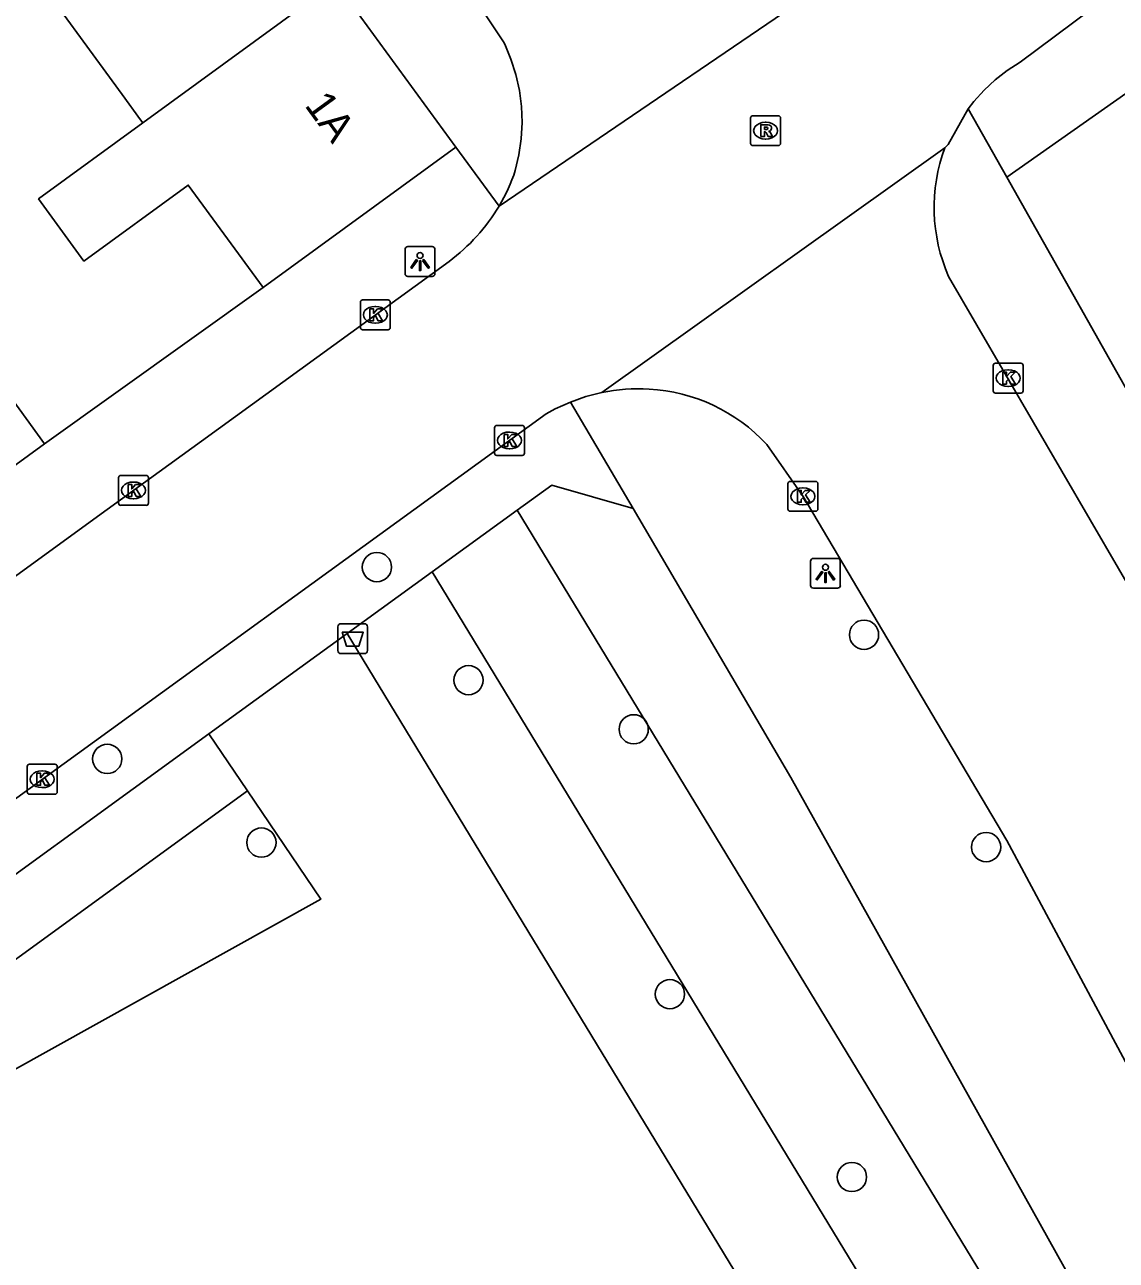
# Model space of a CAD drawing. Extents: x 159222 to 160346, y 381249 to 382166.
# Drawn here: x 159768.58 to 159805.07, y 381427.03 to 381468.35 of the extents above; entities that cross this region are included whole.
import ezdxf

# ---------------------------------------------------------------- set-up
doc = ezdxf.new("R2010")
doc.units = 0
for name, color, linetype in [('IMGEO_Afvalbak', 7, 'Continuous'), ('IMGEO_Boom', 7, 'Continuous'), ('IMGEO_Groenvoorziening', 7, 'Continuous'), ('IMGEO_Kolk', 7, 'Continuous'), ('IMGEO_Lichtpunt', 7, 'Continuous'), ('IMGEO_Muur', 7, 'Continuous'), ('IMGEO_Pand', 7, 'Continuous'), ('IMGEO_Pand_nummerreeks', 7, 'Continuous'), ('IMGEO_Rijbaan_lokaal_gesloten', 7, 'Continuous'), ('IMGEO_Rijbaan_lokaal_open', 7, 'Continuous'), ('IMGEO_Rioolput', 7, 'Continuous'), ('IMGEO_Voetpad_open', 7, 'Continuous')]:
    doc.layers.add(name, color=color, linetype=linetype)

msp = doc.modelspace()

# ---------------------------------------------------------------- linework, layer by layer
at = {"layer": 'IMGEO_Afvalbak'}
for p, q in [((159779.046, 381447.418), (159779.046, 381448.218)), ((159779.046, 381448.218), (159779.046, 381447.418)), ((159779.146, 381448.318), (159779.936, 381448.318)), ((159779.936, 381448.318), (159779.146, 381448.318)), ((159780.036, 381448.218), (159780.036, 381447.418)), ((159780.036, 381447.418), (159780.036, 381448.218)), ((159779.936, 381447.318), (159779.146, 381447.318)), ((159779.146, 381447.318), (159779.936, 381447.318))]:
    msp.add_line(p, q, dxfattribs=at)
msp.add_lwpolyline([(159779.189, 381448.032), (159779.893, 381448.032), (159779.744, 381447.562), (159779.338, 381447.562), (159779.189, 381448.032)], dxfattribs=at)
for centre, start, end in [((159779.146, 381448.218), 90, 180), ((159779.146, 381448.218), 90, 180), ((159779.936, 381448.218), 0, 90), ((159779.936, 381448.218), 360, 90), ((159779.146, 381447.418), 180, 270), ((159779.146, 381447.418), 180, 270), ((159779.936, 381447.418), 270, 0), ((159779.936, 381447.418), 270, 0)]:
    msp.add_arc(centre, 0.1, start, end, dxfattribs=at)
at = {"layer": 'IMGEO_Boom'}
for centre in [(159780.351, 381450.212), (159796.633, 381447.95), (159783.412, 381446.43), (159788.934, 381444.787), (159771.337, 381443.797), (159776.488, 381440.997), (159800.715, 381440.846), (159790.146, 381435.928), (159796.229, 381429.812)]:
    msp.add_circle(centre, 0.489, dxfattribs=at)
at = {"layer": 'IMGEO_Groenvoorziening'}
for points in [[(159785.037, 381452.114), (159802.511, 381423.35)], [(159799.442, 381421.661), (159782.195, 381450.052)], [(159779.353, 381447.989), (159783.63, 381440.949), (159796.372, 381419.973)], [(159774.733, 381444.636), (159776.021, 381442.729)], [(159745.234, 381420.346), (159776.021, 381442.729)], [(159776.021, 381442.729), (159778.473, 381439.101), (159748.724, 381422.549), (159746.885, 381417.737)]]:
    msp.add_lwpolyline(points, dxfattribs=at)
at = {"layer": 'IMGEO_Kolk'}
for p, q in [((159779.797, 381458.223), (159779.797, 381459.075)), ((159779.872, 381459.149), (159780.724, 381459.149)), ((159780.285, 381458.929), (159780.31, 381458.929)), ((159780.798, 381459.075), (159780.798, 381458.223)), ((159780.724, 381458.149), (159779.872, 381458.149)), ((159780.308, 381458.369), (159780.283, 381458.369)), ((159800.951, 381456.107), (159800.951, 381456.959)), ((159801.026, 381457.033), (159801.878, 381457.033)), ((159801.952, 381456.959), (159801.952, 381456.107)), ((159801.439, 381456.813), (159801.464, 381456.813)), ((159801.462, 381456.253), (159801.437, 381456.253)), ((159801.878, 381456.033), (159801.026, 381456.033)), ((159784.281, 381454.023), (159784.281, 381454.875)), ((159784.356, 381454.949), (159785.208, 381454.949)), ((159785.282, 381454.875), (159785.282, 381454.023)), ((159784.769, 381454.729), (159784.794, 381454.729)), ((159784.792, 381454.169), (159784.767, 381454.169)), ((159785.208, 381453.949), (159784.356, 381453.949)), ((159771.711, 381452.352), (159771.711, 381453.204)), ((159771.786, 381453.278), (159772.638, 381453.278)), ((159772.712, 381453.204), (159772.712, 381452.352)), ((159772.199, 381453.058), (159772.224, 381453.058)), ((159794.09, 381452.153), (159794.09, 381453.005)), ((159794.165, 381453.079), (159795.017, 381453.079)), ((159794.578, 381452.859), (159794.603, 381452.859)), ((159795.091, 381453.005), (159795.091, 381452.153)), ((159772.222, 381452.498), (159772.197, 381452.498)), ((159772.638, 381452.278), (159771.786, 381452.278)), ((159795.017, 381452.079), (159794.165, 381452.079)), ((159794.601, 381452.299), (159794.576, 381452.299)), ((159768.661, 381442.69), (159768.661, 381443.542)), ((159768.736, 381443.616), (159769.588, 381443.616)), ((159769.149, 381443.396), (159769.174, 381443.396)), ((159769.662, 381443.542), (159769.662, 381442.69)), ((159769.172, 381442.836), (159769.147, 381442.836)), ((159769.588, 381442.616), (159768.736, 381442.616))]:
    msp.add_line(p, q, dxfattribs=at)
for points in [[(159779.797, 381458.223), (159779.797, 381459.075)], [(159779.872, 381459.149), (159780.724, 381459.149)], [(159780.798, 381459.075), (159780.798, 381458.223)], [(159780.118, 381458.849), (159780.241, 381458.849), (159780.241, 381458.698), (159780.371, 381458.849), (159780.535, 381458.849), (159780.389, 381458.698), (159780.542, 381458.449), (159780.39, 381458.449), (159780.305, 381458.613), (159780.241, 381458.546), (159780.241, 381458.449), (159780.118, 381458.449), (159780.118, 381458.849)], [(159780.724, 381458.149), (159779.872, 381458.149)], [(159800.951, 381456.107), (159800.951, 381456.959)], [(159801.026, 381457.033), (159801.878, 381457.033)], [(159801.952, 381456.959), (159801.952, 381456.107)], [(159801.272, 381456.733), (159801.395, 381456.733), (159801.395, 381456.582), (159801.525, 381456.733), (159801.689, 381456.733), (159801.543, 381456.582), (159801.696, 381456.333), (159801.544, 381456.333), (159801.459, 381456.497), (159801.395, 381456.43), (159801.395, 381456.333), (159801.272, 381456.333), (159801.272, 381456.733)], [(159801.878, 381456.033), (159801.026, 381456.033)], [(159784.281, 381454.023), (159784.281, 381454.875)], [(159784.356, 381454.949), (159785.208, 381454.949)], [(159785.282, 381454.875), (159785.282, 381454.023)], [(159784.602, 381454.649), (159784.725, 381454.649), (159784.725, 381454.498), (159784.855, 381454.649), (159785.019, 381454.649), (159784.873, 381454.498), (159785.026, 381454.249), (159784.874, 381454.249), (159784.789, 381454.413), (159784.725, 381454.346), (159784.725, 381454.249), (159784.602, 381454.249), (159784.602, 381454.649)], [(159785.208, 381453.949), (159784.356, 381453.949)], [(159771.711, 381452.352), (159771.711, 381453.204)], [(159771.786, 381453.278), (159772.638, 381453.278)], [(159772.712, 381453.204), (159772.712, 381452.352)], [(159772.032, 381452.978), (159772.155, 381452.978), (159772.155, 381452.827), (159772.285, 381452.978), (159772.449, 381452.978), (159772.303, 381452.827), (159772.456, 381452.578), (159772.304, 381452.578), (159772.219, 381452.742), (159772.155, 381452.675), (159772.155, 381452.578), (159772.032, 381452.578), (159772.032, 381452.978)], [(159794.09, 381452.153), (159794.09, 381453.005)], [(159794.165, 381453.079), (159795.017, 381453.079)], [(159794.411, 381452.779), (159794.534, 381452.779), (159794.534, 381452.628), (159794.664, 381452.779), (159794.828, 381452.779), (159794.682, 381452.628), (159794.835, 381452.379), (159794.683, 381452.379), (159794.598, 381452.543), (159794.534, 381452.476), (159794.534, 381452.379), (159794.411, 381452.379), (159794.411, 381452.779)], [(159795.091, 381453.005), (159795.091, 381452.153)], [(159772.638, 381452.278), (159771.786, 381452.278)], [(159795.017, 381452.079), (159794.165, 381452.079)], [(159768.661, 381442.69), (159768.661, 381443.542)], [(159768.736, 381443.616), (159769.588, 381443.616)], [(159768.982, 381443.316), (159769.105, 381443.316), (159769.105, 381443.165), (159769.235, 381443.316), (159769.399, 381443.316), (159769.253, 381443.165), (159769.406, 381442.916), (159769.254, 381442.916), (159769.169, 381443.08), (159769.105, 381443.013), (159769.105, 381442.916), (159768.982, 381442.916), (159768.982, 381443.316)], [(159769.662, 381443.542), (159769.662, 381442.69)], [(159769.588, 381442.616), (159768.736, 381442.616)]]:
    msp.add_lwpolyline(points, dxfattribs=at)
for centre, start, end in [((159779.874, 381459.073), 91.552, 178.448), ((159779.874, 381459.073), 91.552, 178.448), ((159780.722, 381459.073), 1.552, 88.448), ((159780.722, 381459.073), 1.552, 88.448), ((159779.874, 381458.225), 181.552, 268.448), ((159779.874, 381458.225), 181.552, 268.448), ((159780.722, 381458.225), 271.552, 358.448), ((159780.722, 381458.225), 271.552, 358.448), ((159801.028, 381456.957), 91.552, 178.448), ((159801.028, 381456.957), 91.552, 178.448), ((159801.876, 381456.957), 1.552, 88.448), ((159801.876, 381456.957), 1.552, 88.448), ((159801.028, 381456.109), 181.552, 268.448), ((159801.028, 381456.109), 181.552, 268.448), ((159801.876, 381456.109), 271.552, 358.448), ((159801.876, 381456.109), 271.552, 358.448), ((159784.358, 381454.873), 91.552, 178.448), ((159784.358, 381454.873), 91.552, 178.448), ((159785.206, 381454.873), 1.552, 88.448), ((159785.206, 381454.873), 1.552, 88.448), ((159784.358, 381454.025), 181.552, 268.448), ((159784.358, 381454.025), 181.552, 268.448), ((159785.206, 381454.025), 271.552, 358.448), ((159785.206, 381454.025), 271.552, 358.448), ((159771.788, 381453.202), 91.552, 178.448), ((159771.788, 381453.202), 91.552, 178.448), ((159772.636, 381453.202), 1.552, 88.448), ((159772.636, 381453.202), 1.552, 88.448), ((159794.167, 381453.003), 91.552, 178.448), ((159794.167, 381453.003), 91.552, 178.448), ((159795.015, 381453.003), 1.552, 88.448), ((159795.015, 381453.003), 1.552, 88.448), ((159771.788, 381452.354), 181.552, 268.448), ((159771.788, 381452.354), 181.552, 268.448), ((159772.636, 381452.354), 271.552, 358.448), ((159772.636, 381452.354), 271.552, 358.448), ((159794.167, 381452.155), 181.552, 268.448), ((159794.167, 381452.155), 181.552, 268.448), ((159795.015, 381452.155), 271.552, 358.448), ((159795.015, 381452.155), 271.552, 358.448), ((159768.738, 381443.54), 91.552, 178.448), ((159768.738, 381443.54), 91.552, 178.448), ((159769.586, 381443.54), 1.552, 88.448), ((159769.586, 381443.54), 1.552, 88.448), ((159768.738, 381442.692), 181.552, 268.448), ((159768.738, 381442.692), 181.552, 268.448), ((159769.586, 381442.692), 271.552, 358.448), ((159769.586, 381442.692), 271.552, 358.448)]:
    msp.add_arc(centre, 0.0765, start, end, dxfattribs=at)
for centre, major_axis, ratio, start_param, end_param in [((159780.284, 381458.649), (-0.387, 0.002), 0.722429, 4.712389, 7.853982), ((159780.309, 381458.649), (-0.39, 0.002), 0.717154, 1.570796, 4.712389), ((159801.438, 381456.533), (-0.387, 0.002), 0.722429, 4.712389, 7.853982), ((159801.463, 381456.533), (-0.39, 0.002), 0.717154, 1.570796, 4.712389), ((159784.768, 381454.449), (-0.387, 0.002), 0.722429, 4.712389, 7.853982), ((159784.793, 381454.449), (-0.39, 0.002), 0.717154, 1.570796, 4.712389), ((159772.198, 381452.778), (-0.387, 0.002), 0.722429, 4.712389, 7.853982), ((159772.223, 381452.778), (-0.39, 0.002), 0.717154, 1.570796, 4.712389), ((159794.577, 381452.579), (-0.387, 0.002), 0.722429, 4.712389, 7.853982), ((159794.602, 381452.579), (-0.39, 0.002), 0.717154, 1.570796, 4.712389), ((159769.148, 381443.116), (-0.387, 0.002), 0.722429, 4.712389, 7.853982), ((159769.173, 381443.116), (-0.39, 0.002), 0.717154, 1.570796, 4.712389)]:
    msp.add_ellipse(centre, major_axis=major_axis, ratio=ratio, start_param=start_param, end_param=end_param, dxfattribs=at)
at = {"layer": 'IMGEO_Lichtpunt'}
for p, q in [((159781.293, 381460.836), (159781.293, 381460.029)), ((159781.293, 381460.836), (159781.293, 381460.029)), ((159782.195, 381460.931), (159781.387, 381460.931)), ((159782.195, 381460.931), (159781.387, 381460.931)), ((159782.289, 381460.029), (159782.289, 381460.836)), ((159782.289, 381460.029), (159782.289, 381460.836)), ((159781.387, 381459.935), (159782.195, 381459.935)), ((159781.387, 381459.935), (159782.195, 381459.935)), ((159794.845, 381450.407), (159794.845, 381449.6)), ((159794.845, 381450.407), (159794.845, 381449.6)), ((159795.747, 381450.502), (159794.939, 381450.502)), ((159795.747, 381450.502), (159794.939, 381450.502)), ((159795.841, 381449.6), (159795.841, 381450.407)), ((159795.841, 381449.6), (159795.841, 381450.407)), ((159794.939, 381449.506), (159795.747, 381449.506)), ((159794.939, 381449.506), (159795.747, 381449.506))]:
    msp.add_line(p, q, dxfattribs=at)
for points in [[(159781.667, 381460.5), (159781.706, 381460.472), (159781.518, 381460.21), (159781.48, 381460.237), (159781.667, 381460.5)], [(159781.769, 381460.452), (159781.816, 381460.452), (159781.816, 381460.13), (159781.769, 381460.13), (159781.769, 381460.452)], [(159781.879, 381460.472), (159781.917, 381460.499), (159782.104, 381460.237), (159782.065, 381460.209), (159781.879, 381460.472)], [(159795.219, 381450.071), (159795.258, 381450.043), (159795.07, 381449.781), (159795.032, 381449.808), (159795.219, 381450.071)], [(159795.321, 381450.023), (159795.368, 381450.023), (159795.368, 381449.701), (159795.321, 381449.701), (159795.321, 381450.023)], [(159795.431, 381450.043), (159795.469, 381450.07), (159795.656, 381449.808), (159795.617, 381449.78), (159795.431, 381450.043)]]:
    msp.add_lwpolyline(points, dxfattribs=at)
for centre in [(159781.792, 381460.634), (159795.344, 381450.205)]:
    msp.add_circle(centre, 0.0994, dxfattribs=at)
for centre, start, end in [((159781.387, 381460.836), 90, 180), ((159781.387, 381460.836), 90, 180), ((159782.195, 381460.836), 0, 90), ((159782.195, 381460.836), 0, 90), ((159781.387, 381460.029), 180, 270), ((159781.387, 381460.029), 180, 270), ((159782.195, 381460.029), 270, 0), ((159782.195, 381460.029), 270, 360), ((159794.939, 381450.407), 90, 180), ((159794.939, 381450.407), 90, 180), ((159795.747, 381450.407), 0, 90), ((159795.747, 381450.407), 0, 90), ((159794.939, 381449.6), 180, 270), ((159794.939, 381449.6), 180, 270), ((159795.747, 381449.6), 270, 0), ((159795.747, 381449.6), 270, 360)]:
    msp.add_arc(centre, 0.0946, start, end, dxfattribs=at)
at = {"layer": 'IMGEO_Muur'}
msp.add_lwpolyline([(159769.241, 381454.339), (159776.549, 381459.559)], dxfattribs=at)
at = {"layer": 'IMGEO_Pand'}
for points in [[(159801.406, 381463.25), (159812.627, 381471.155), (159814.489, 381472.466)], [(159768.589, 381470.465), (159771.832, 381466.021), (159772.451, 381465.173), (159772.525, 381465.072)], [(159778.966, 381469.772), (159772.525, 381465.072)], [(159778.966, 381469.772), (159782.989, 381464.259)], [(159772.525, 381465.072), (159769.038, 381462.527), (159770.555, 381460.447), (159774.043, 381462.992), (159776.549, 381459.559)], [(159782.989, 381464.259), (159776.549, 381459.559)], [(159809.148, 381449.52), (159801.406, 381463.25)], [(159762.739, 381457.872), (159765.318, 381459.744), (159769.241, 381454.339)], [(159769.241, 381454.339), (159766.676, 381452.477)]]:
    msp.add_lwpolyline(points, dxfattribs=at)
at = {"layer": 'IMGEO_Rijbaan_lokaal_gesloten'}
for points in [[(159787.872, 381456.049), (159799.332, 381464.238)], [(159799.461, 381459.93), (159807.03, 381446.91)], [(159807.676, 381429.366), (159801.407, 381441.063), (159794.594, 381452.576), (159793.382, 381454.313)]]:
    msp.add_lwpolyline(points, dxfattribs=at)
for centre, radius, start, end in [((159804.758, 381462.245), 5.781, 159.8284, 203.6019), ((159789.123, 381449.926), 6.25, 87.0179, 101.546), ((159789.118, 381450.367), 5.81, 42.7866, 86.7466)]:
    msp.add_arc(centre, radius, start, end, dxfattribs=at)
at = {"layer": 'IMGEO_Rijbaan_lokaal_open'}
for points in [[(159800.114, 381465.542), (159800.306, 381465.789), (159800.646, 381466.167), (159801.019, 381466.514), (159801.421, 381466.825), (159801.849, 381467.1), (159808.9, 381472.368), (159810.846, 381473.748), (159812.928, 381475.224), (159813.774, 381475.824), (159816.088, 381477.412), (159825.099, 381483.598), (159827.05, 381484.957), (159830.152, 381487.119), (159834.029, 381489.821)], [(159774.841, 381481.496), (159775.507, 381480.628), (159780.458, 381473.977), (159784.579, 381467.786), (159784.622, 381467.698), (159784.831, 381467.199), (159784.994, 381466.684), (159785.111, 381466.156), (159785.18, 381465.62), (159785.201, 381465.08), (159785.174, 381464.54), (159785.099, 381464.004), (159784.976, 381463.478)], [(159784.432, 381462.289), (159797.283, 381471.041)], [(159800.114, 381465.542), (159799.442, 381464.347), (159799.332, 381464.238)], [(159762.389, 381445.632), (159765.811, 381448.121), (159771.014, 381451.905), (159774.481, 381454.427), (159782.761, 381460.436)], [(159786.816, 381455.733), (159787.337, 381455.915), (159787.872, 381456.049)], [(159765.923, 381440.763), (159767.044, 381441.581), (159786.01, 381455.342), (159786.313, 381455.506), (159786.816, 381455.733)]]:
    msp.add_lwpolyline(points, dxfattribs=at)
for centre, radius, start, end in [((159779.041, 381465.474), 6.262, 329.4216, 341.4076), ((159779.029, 381465.481), 6.275, 306.489, 329.4239)]:
    msp.add_arc(centre, radius, start, end, dxfattribs=at)
at = {"layer": 'IMGEO_Rioolput'}
for p, q in [((159792.843, 381464.384), (159792.843, 381465.236)), ((159792.918, 381465.31), (159793.77, 381465.31)), ((159793.844, 381465.236), (159793.844, 381464.384)), ((159793.331, 381465.09), (159793.356, 381465.09)), ((159793.77, 381464.31), (159792.918, 381464.31)), ((159793.354, 381464.53), (159793.329, 381464.53))]:
    msp.add_line(p, q, dxfattribs=at)
for points in [[(159792.843, 381464.384), (159792.843, 381465.236)], [(159792.918, 381465.31), (159793.77, 381465.31)], [(159793.844, 381465.236), (159793.844, 381464.384)], [(159793.432, 381465.008), (159793.18, 381465.01), (159793.18, 381464.61)], [(159793.18, 381464.61), (159793.304, 381464.61), (159793.304, 381464.772), (159793.315, 381464.772)], [(159793.358, 381464.929), (159793.304, 381464.929), (159793.304, 381464.848)], [(159793.304, 381464.848), (159793.356, 381464.848)], [(159793.362, 381464.743), (159793.433, 381464.61), (159793.573, 381464.61), (159793.508, 381464.736)], [(159793.77, 381464.31), (159792.918, 381464.31)]]:
    msp.add_lwpolyline(points, dxfattribs=at)
for centre, radius, start, end in [((159792.92, 381465.234), 0.0765, 91.552, 178.448), ((159792.92, 381465.234), 0.0765, 91.552, 178.448), ((159793.768, 381465.234), 0.0765, 1.552, 88.448), ((159793.768, 381465.234), 0.0765, 1.552, 88.448), ((159793.314, 381464.719), 0.0533, 26.0293, 88.6989), ((159793.34, 381465.037), 0.19, 274.7715, 282.9687), ((159793.364, 381464.833), 0.0964, 77.0061, 93.1865), ((159793.378, 381464.89), 0.0378, 276.6634, 79.6772), ((159793.431, 381464.898), 0.109, 350.3612, 89.416), ((159793.429, 381464.898), 0.112, 277.5842, 350.9817), ((159793.413, 381464.683), 0.108, 29.5134, 73.7905), ((159792.92, 381464.386), 0.0765, 181.552, 268.448), ((159792.92, 381464.386), 0.0765, 181.552, 268.448), ((159793.768, 381464.386), 0.0765, 271.552, 358.448), ((159793.768, 381464.386), 0.0765, 271.552, 358.448)]:
    msp.add_arc(centre, radius, start, end, dxfattribs=at)
for centre, major_axis, ratio, start_param, end_param in [((159793.33, 381464.81), (-0.387, 0.002), 0.722429, 4.712389, 7.853982), ((159793.355, 381464.81), (-0.39, 0.002), 0.717154, 1.570796, 4.712389)]:
    msp.add_ellipse(centre, major_axis=major_axis, ratio=ratio, start_param=start_param, end_param=end_param, dxfattribs=at)
at = {"layer": 'IMGEO_Voetpad_open'}
for points in [[(159801.406, 381463.25), (159800.114, 381465.542)], [(159784.432, 381462.289), (159782.989, 381464.259)], [(159776.549, 381459.559), (159769.241, 381454.339)], [(159786.816, 381455.733), (159788.915, 381452.168)], [(159785.037, 381452.114), (159786.193, 381452.953), (159788.915, 381452.168)], [(159782.195, 381450.052), (159785.037, 381452.114)], [(159788.915, 381452.168), (159794.183, 381443.173), (159804.609, 381424.503)], [(159779.353, 381447.989), (159782.195, 381450.052)], [(159774.733, 381444.636), (159779.353, 381447.989)], [(159744.001, 381422.294), (159774.733, 381444.636)]]:
    msp.add_lwpolyline(points, dxfattribs=at)

# ---------------------------------------------------------------- texts
at = {"layer": 'IMGEO_Pand_nummerreeks'}
msp.add_text('1A', height=1, rotation=306.119, dxfattribs=at).set_placement((159777.908, 381465.657))

doc.saveas('drawing.dxf')
